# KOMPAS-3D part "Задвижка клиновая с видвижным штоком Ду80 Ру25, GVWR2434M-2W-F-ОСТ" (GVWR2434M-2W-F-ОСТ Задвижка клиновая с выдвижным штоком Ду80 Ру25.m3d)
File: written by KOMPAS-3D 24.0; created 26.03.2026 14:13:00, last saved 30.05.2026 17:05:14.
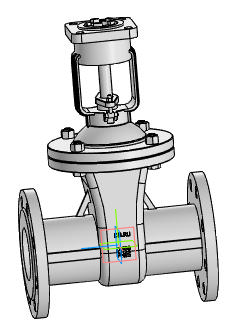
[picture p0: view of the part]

Document properties: Автор: R2D2; Полное имя файла: E:\Работа\Зайцев\GVWR2434M-2W-F-ОСТ Задвижка клиновая с выдвижным штоком DN.ru Ду50-300 Ру25\исходные материалы\DN80\DN80\GVWR2434M-2W-F-ОСТ Задвижка клиновая с выдвижным штоком Ду80 Ру25.m3d

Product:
- Part/product: Задвижка клиновая с видвижным штоком Ду80 Ру25  | designation GVWR2434M-2W-F-ОСТ
    Масса: 24
    Раздел спецификации: Прочие изделия
    Примечание: D040-07587

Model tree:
1. Операция без истории:1

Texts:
  GVWR2434M-2W-F-ОСТ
